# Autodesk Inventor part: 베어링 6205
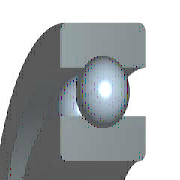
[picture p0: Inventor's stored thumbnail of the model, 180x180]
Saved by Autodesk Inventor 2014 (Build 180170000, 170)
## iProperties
Created: 2015-10
Part Number: 베어링 6205
Material: 강, 연강
Description: 깊은 그루브 볼 베어링
Document SubType Name: Modeling
Standard: KS B 2023
Designer: mdu
Standards Organization: KS
Language: ko-KR
Size Designation: 6205 - 25 x 52 x 15
Categories: <MemberInstance><Categories><Category DisplayName="샤프트 부품" InternalName="7f7aeb1f-a693-4053-b835-cee3144e0d98" Mnemonic="SHFT"><Category DisplayName="베어링" Inter
Density: 1 g/cm^3
Appearance: 노란색
IsCustomPart: 1
Author: mdu
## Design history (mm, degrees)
sketch "스케치" dims "d0" = 7.02 (= -0.26 x WD + 0.26 x BD)
  geometry: L1 (3.99, 19.25)-(11.01, 19.25); L2 (7.5, 19.25)-(7.5, 15.74); L3 (7.5, 19.25)-(7.5, 22.76); L4 (4.892, 16.901)-(0, 16.901); L5 (0, 12.5)-(15, 12.5); L6 (4.892, 21.599)-(0, 21.599); L7 (0, 26)-(15, 26); L8 (15, 12.5)-(15, 16.901); L9 (10.108, 16.901)-(15, 16.901); L10 (10.108, 21.599)-(15, 21.599); L11 (15, 26)-(15, 21.599); L12 (-1.4, 0)-(8.4, 0) reference; L13 (0, -0.3)-(0, 5.3) reference
  constraints: 22 end point, 4 point on line, 2 collinear, 2 perpendicular, 2 symmetric about line, 1 midpoint, 1 parallel, 14 other
  dimensions: "d9" = 25 diameter of L5 L12 (= WD); "d11" = 52 diameter of L7 L12 (= BD); "d12" = 15 distance between parallel lines of L8 L13 (= KB); "d13" = 33.802 diameter of L9 L12 (= 0.326 x BD + 0.674 x WD)
revolve "본체" stored, may be unused: angle "d6" = 90 deg
revolve "볼" stored, may be unused: angle "d7" = 90 deg
pattern_circular "IDS_ARRAYBALL[SIMPL:T]" dims angle "d3" = 360 deg
body "Solid1"
fillet "모깎기1" dims "d1" = 1 (= KRS)
other parameters: "WD" = 25 [user parameter; used in 5 equation terms], "BD" = 52 [user parameter; used in 5 equation terms], "KB" = 15 [user parameter; used in 1 equation term], "KRS" = 1 [user parameter; used in 1 equation term], "d4" = 0, "d5" = 0, "d8" = 0, "d14" = 0, "d15" = 0, "BBA" = 0 [user parameter], "BC0" = 7800000 [user parameter], "BC" = 1.4e+07 [user parameter], "BR" = 26 (= 0.5 x BD) [user parameter], "WR" = 12.5 (= 0.5 x WD) [user parameter]
